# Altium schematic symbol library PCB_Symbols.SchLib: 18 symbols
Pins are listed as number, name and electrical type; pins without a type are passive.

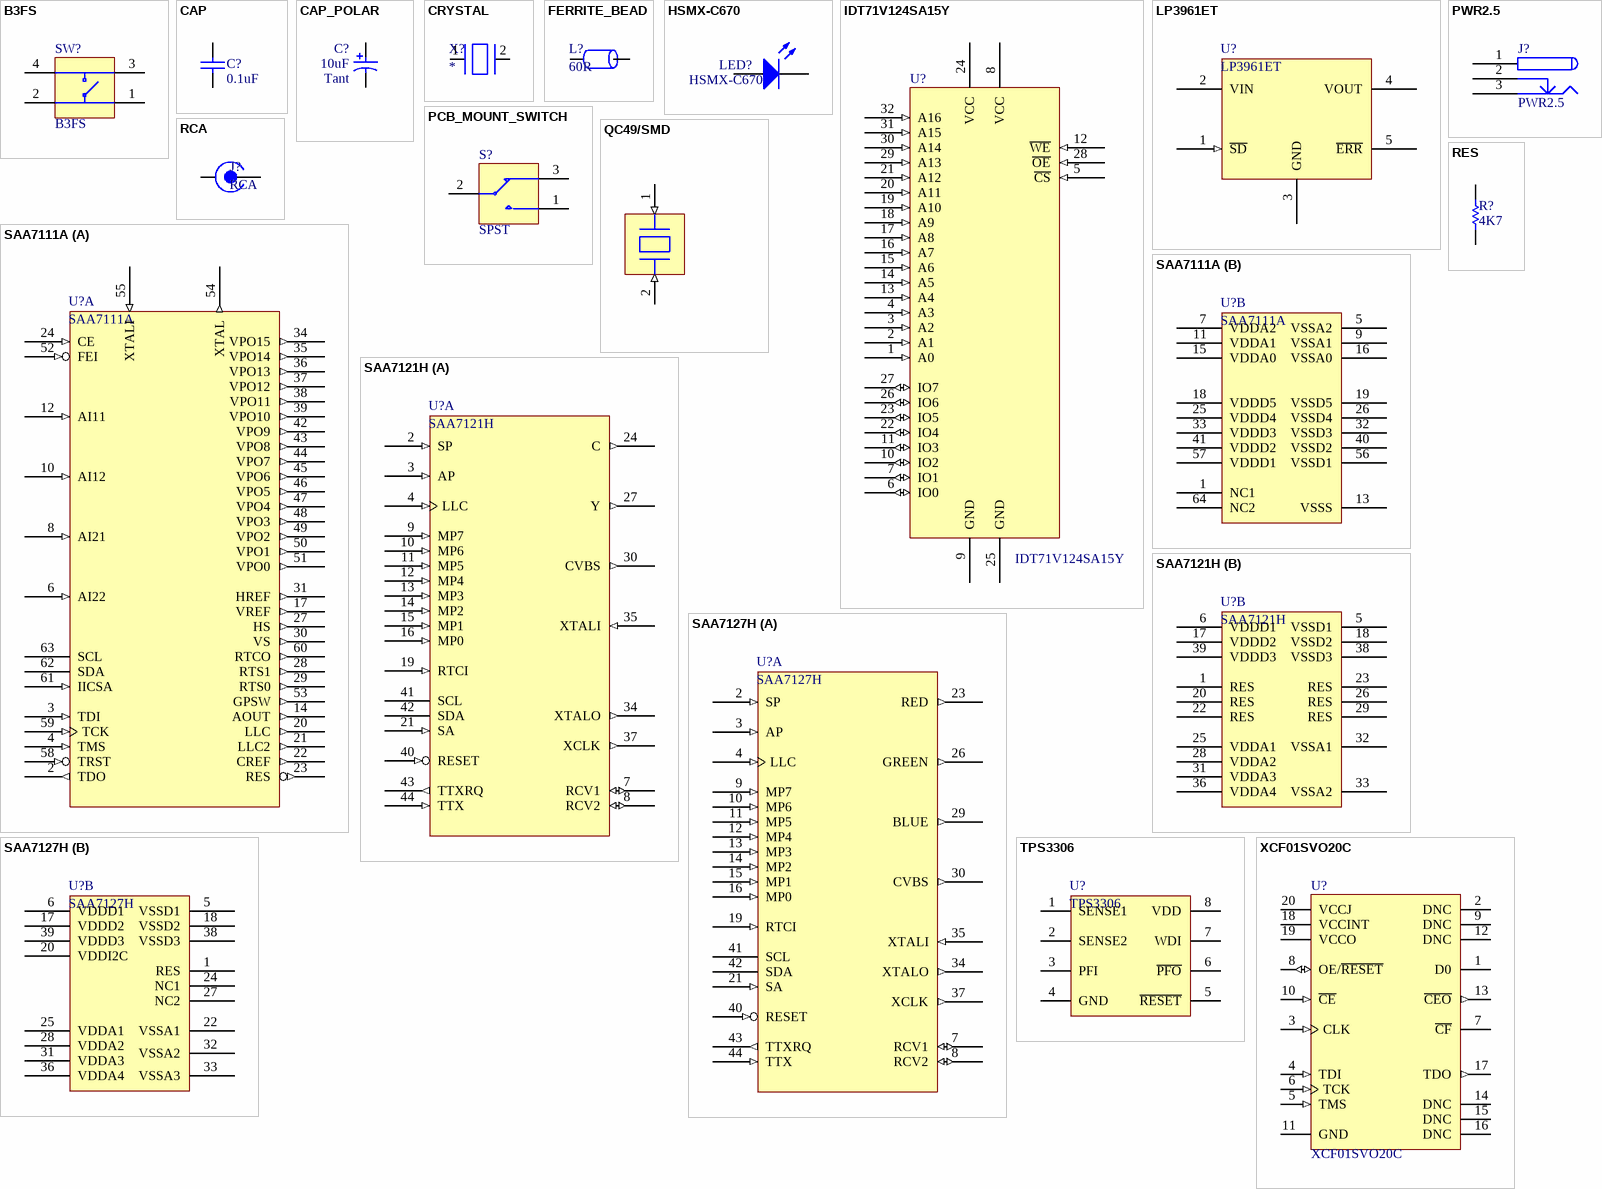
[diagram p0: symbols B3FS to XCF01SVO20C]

## B3FS
designator SW?
SPNA SMD Keyboard Switch; Fitted: True
footprint B3FS_SWITCH
pins: 1, 2, 3, 4

## CAP
designator C?, comment 0.1uF
Capacitor; Fitted: True
footprint CC1005-0402 (0402 Capacitor)
footprint CC1608-0603 (0603 Capacitor)
footprint CC2012-0805
footprint CC3216-1206 (1206 Capacitor)
footprint CC3225-1210 (1210 Capacitor)
pins: 1, 2

## CAP_POLAR
designator C?, comment 10uF  Capacitor Type: Tant
Polar Capacitor; Fitted: True
footprint MCCT-A (3216 Polar Capacitor)
footprint MCCT-B
footprint MCCT-C (6032 Polar Capacitor)
footprint MCCT-D (7343 Polar Capacitor)
footprint RB8/3.5
pins: 1, 2

## CRYSTAL
designator X?
pins: 1, 2

## FERRITE_BEAD
designator L?, comment 60R
BMB Series Ferrite Chip Bead
footprint CC2012-0805
pins: 1, 2

## HSMX-C670
designator LED?
Typical RED GaAs SMD LED Agilent make; Manufacturer: Generic Components; Class I: Optoelectronic; Fitted: True
footprint SMD _LED
simulation model LED1 (Diode)
pins: 1 A, 2 K

## IDT71V124SA15Y
designator U?
128K x 8 bit Fast Static RAM; Fitted: True
footprint SO-J32
pins: 1 A0 (in) "Address 0", 2 A1 (in) "Address 1", 3 A2 (in) "Address 3", 4 A3 (in) "Address 3", 5 ~{CS} (in) "Chip Select", 6 IO0 (io) "Data 0", 7 IO1 (io) "Data 1", 8 VCC (power) "Pos Supply", 9 GND (power), 10 IO2 (io) "Data 2", 11 IO3 (io) "Data 3", 12 ~{WE} (in) "Write Enable", 13 A4 (in) "Address 4", 14 A5 (in) "Address 5", 15 A6 (in) "Address 6", 16 A7 (in) "Address 7", 17 A8 (in) "Address 8", 18 A9 (in) "Address 9", 19 A10 (in) "Address 10", 20 A11 (in) "Address 11", 21 A12 (in) "Address 12", 22 IO4 (io) "Data 4", 23 IO5 (io) "Data 5", 24 VCC (power) "Pos Supply", 25 GND (power), 26 IO6 (io) "Data 6", 27 IO7 (io) "Data 7", 28 ~{OE} (in) "Output Enable", 29 A13 (in) "Address 13", 30 A14 (in) "Address 14", 31 A15 (in) "Address 15", 32 A16 (in) "Address 16"

## LP3961ET
designator U?
800mA Fast UL Dropout Regulator
pins: 1 ~{SD} (in), 2 VIN (power), 3 GND (power), 4 VOUT (power), 5 ~{ERR} (oc)

## PCB_MOUNT_SWITCH
designator S?, comment SPST
SPDT Subminiature Toggle Switch; Fitted: True
footprint PCB_SWITCH
pins: 1, 2, 3

## PWR2.5
designator J?
Low Voltage Power Supply Sonnector; Fitted: True
footprint PWR2.5
pins: 1 (power), 2 (power), 3 (power)

## QC49/SMD
designator CR?
SMD Crystal 20MHz HY-Q; Fitted: True
footprint QC49/SMD (SMD Crystal)
footprint QC49/SMD (SMD Crystal)
pins: 1 (in), 2 (in)

## RCA
designator J?
RCA Socket
footprint RCA_MR551L (Schurter RCA PCB Socket (Farnell 152-396))
pins: 1, 2

## RES
designator R?, comment 4K7
Resistor; Fitted: True
footprint CC1005-0402 (0402 Resistor)
footprint CC1310-0504 (0504 Resistor)
footprint CC1608-0603 (0603 Resistor)
footprint CC2012-0805
footprint CC3216-1206 (1206 Resistor)
footprint CC3225-1210 (1210 Resistor)
footprint CC4513-1805 (1805 Resistor)
footprint CC2512 (2512 Resistor)
footprint CC3225-0805
footprint CC1202-0805
pins: 1, 2

## SAA7111A
designator U?
Philips Enhanced Video Input Processor
part A pins: 2 TDO (out), 3 TDI (in), 4 TMS (in), 6 AI22 (in), 8 AI21 (in), 10 AI12 (in), 12 AI11 (in), 14 AOUT (out), 17 VREF (out), 20 LLC (out), 21 LLC2 (out), 22 CREF (out), 23 RES (out), 24 CE (in), 27 HS (out), 28 RTS1 (out), 29 RTS0 (out), 30 VS (out), 31 HREF (out), 34 VPO15 (out), 35 VPO14 (out), 36 VPO13 (out), 37 VPO12 (out), 38 VPO11 (out), 39 VPO10 (out), 42 VPO9 (out), 43 VPO8 (out), 44 VPO7 (out), 45 VPO6 (out), 46 VPO5 (out), 47 VPO4 (out), 48 VPO3 (out), 49 VPO2 (out), 50 VPO1 (out), 51 VPO0 (out), 52 FEI (in), 53 GPSW (out), 54 XTAL (out), 55 XTALI (in), 58 TRST (in), 59 TCK (in), 60 RTCO (out), 61 IICSA (in), 62 SDA (oc), 63 SCL (oc)
part B pins: 1 NC1, 5 VSSA2 (power), 7 VDDA2 (power), 9 VSSA1 (power), 11 VDDA1 (power), 13 VSSS (power), 15 VDDA0 (power), 16 VSSA0 (power), 18 VDDD5 (power), 19 VSSD5 (power), 25 VDDD4 (power), 26 VSSD4 (power), 32 VSSD3 (power), 33 VDDD3 (power), 40 VSSD2 (power), 41 VDDD2 (power), 56 VSSD1 (power), 57 VDDD1 (power), 64 NC2

## SAA7121H
designator U?
Philips Digital Video Encoder
part A pins: 2 SP (in), 3 AP (in), 4 LLC (in), 7 RCV1 (io), 8 RCV2 (io), 9 MP7 (in), 10 MP6 (in), 11 MP5 (in), 12 MP4 (in), 13 MP3 (in), 14 MP2 (in), 15 MP1 (in), 16 MP0 (in), 19 RTCI (in), 21 SA (in), 24 C (out), 27 Y (out), 30 CVBS (out), 34 XTALO (out), 35 XTALI (in), 37 XCLK (out), 40 RESET (in), 41 SCL (oc), 42 SDA (oc), 43 TTXRQ (out), 44 TTX (in)
part B pins: 1 RES, 5 VSSD1 (power), 6 VDDD1 (power), 17 VDDD2 (power), 18 VSSD2 (power), 20 RES, 22 RES, 23 RES, 25 VDDA1 (power), 26 RES, 28 VDDA2 (power), 29 RES, 31 VDDA3 (power), 32 VSSA1 (power), 33 VSSA2 (power), 36 VDDA4 (power), 38 VSSD3 (power), 39 VDDD3 (power)

## SAA7127H
designator U?
Philips Digital Video Encoder
footprint QFP10X10_44
part A pins: 2 SP (in), 3 AP (in), 4 LLC (in), 7 RCV1 (io), 8 RCV2 (io), 9 MP7 (in), 10 MP6 (in), 11 MP5 (in), 12 MP4 (in), 13 MP3 (in), 14 MP2 (in), 15 MP1 (in), 16 MP0 (in), 19 RTCI (in), 21 SA (in), 23 RED (out), 26 GREEN (out), 29 BLUE (out), 30 CVBS (out), 34 XTALO (out), 35 XTALI (in), 37 XCLK (out), 40 RESET (in), 41 SCL (oc), 42 SDA (oc), 43 TTXRQ (out), 44 TTX (in)
part B pins: 1 RES, 5 VSSD1 (power), 6 VDDD1 (power), 17 VDDD2 (power), 18 VSSD2 (power), 20 VDDI2C (power), 22 VSSA1 (power), 24 NC1, 25 VDDA1 (power), 27 NC2, 28 VDDA2 (power), 31 VDDA3 (power), 32 VSSA2 (power), 33 VSSA3 (power), 36 VDDA4 (power), 38 VSSD3 (power), 39 VDDD3 (power)

## TPS3306
designator U?
TI Dual Voltage MPU Supervisory Circuit
footprint SOIC8
pins: 1 SENSE1, 2 SENSE2, 3 PFI, 4 GND (power), 5 ~{RESET} (oc), 6 ~{PFO} (oc), 7 WDI, 8 VDD (power)

## XCF01SVO20C
designator U?
XCF00S Series, Platform Flash In-System Programmable Configuration 3.3V PROM, 1-Megabit, Commercial Grade; Manufacturer: Xilinx; Package Information: Latest Revision: ver1.0, May-2003; Class I: Memory; Code - JEDEC: MO-153-AC; Fitted: True
footprint VO20
pins: 1 D0 (hiz) "Serial Data Output, for configuring an FPGA in serial mode.", 2 DNC "Leave Unconnected.", 3 CLK (in) "Configuration Clock Input.", 4 TDI (in) "JTAG Serial Data Input.", 5 TMS (in) "JTAG Mode Select Input.", 6 TCK (in) "JTAG Test Clock Input.", 7 ~{CF} (oc) "Configuration Pulse (Open-Drain Output).", 8 OE/~{RESET} (io) "Output Enable/Reset (Open-Drain I/O).", 9 DNC "Leave Unconnected.", 10 ~{CE} (in) "Chip Enable Input.", 11 GND (power) "Ground", 12 DNC "Leave Unconnected.", 13 ~{CEO} (out) "Chip Enable Output, connects to the CE input of the next PROM in the chain.", 14 DNC "Leave Unconnected.", 15 DNC "Leave Unconnected.", 16 DNC "Leave Unconnected.", 17 TDO (out) "JTAG Serial Data Output.", 18 VCCINT (power) "+3.3V Supply for internal logic.", 19 VCCO (power) "+3.3V, 2.5V, or 1.8V I/O Supply.", 20 VCCJ (power) "+3.3V or 2.5V JTAG Signals I/O Supply."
